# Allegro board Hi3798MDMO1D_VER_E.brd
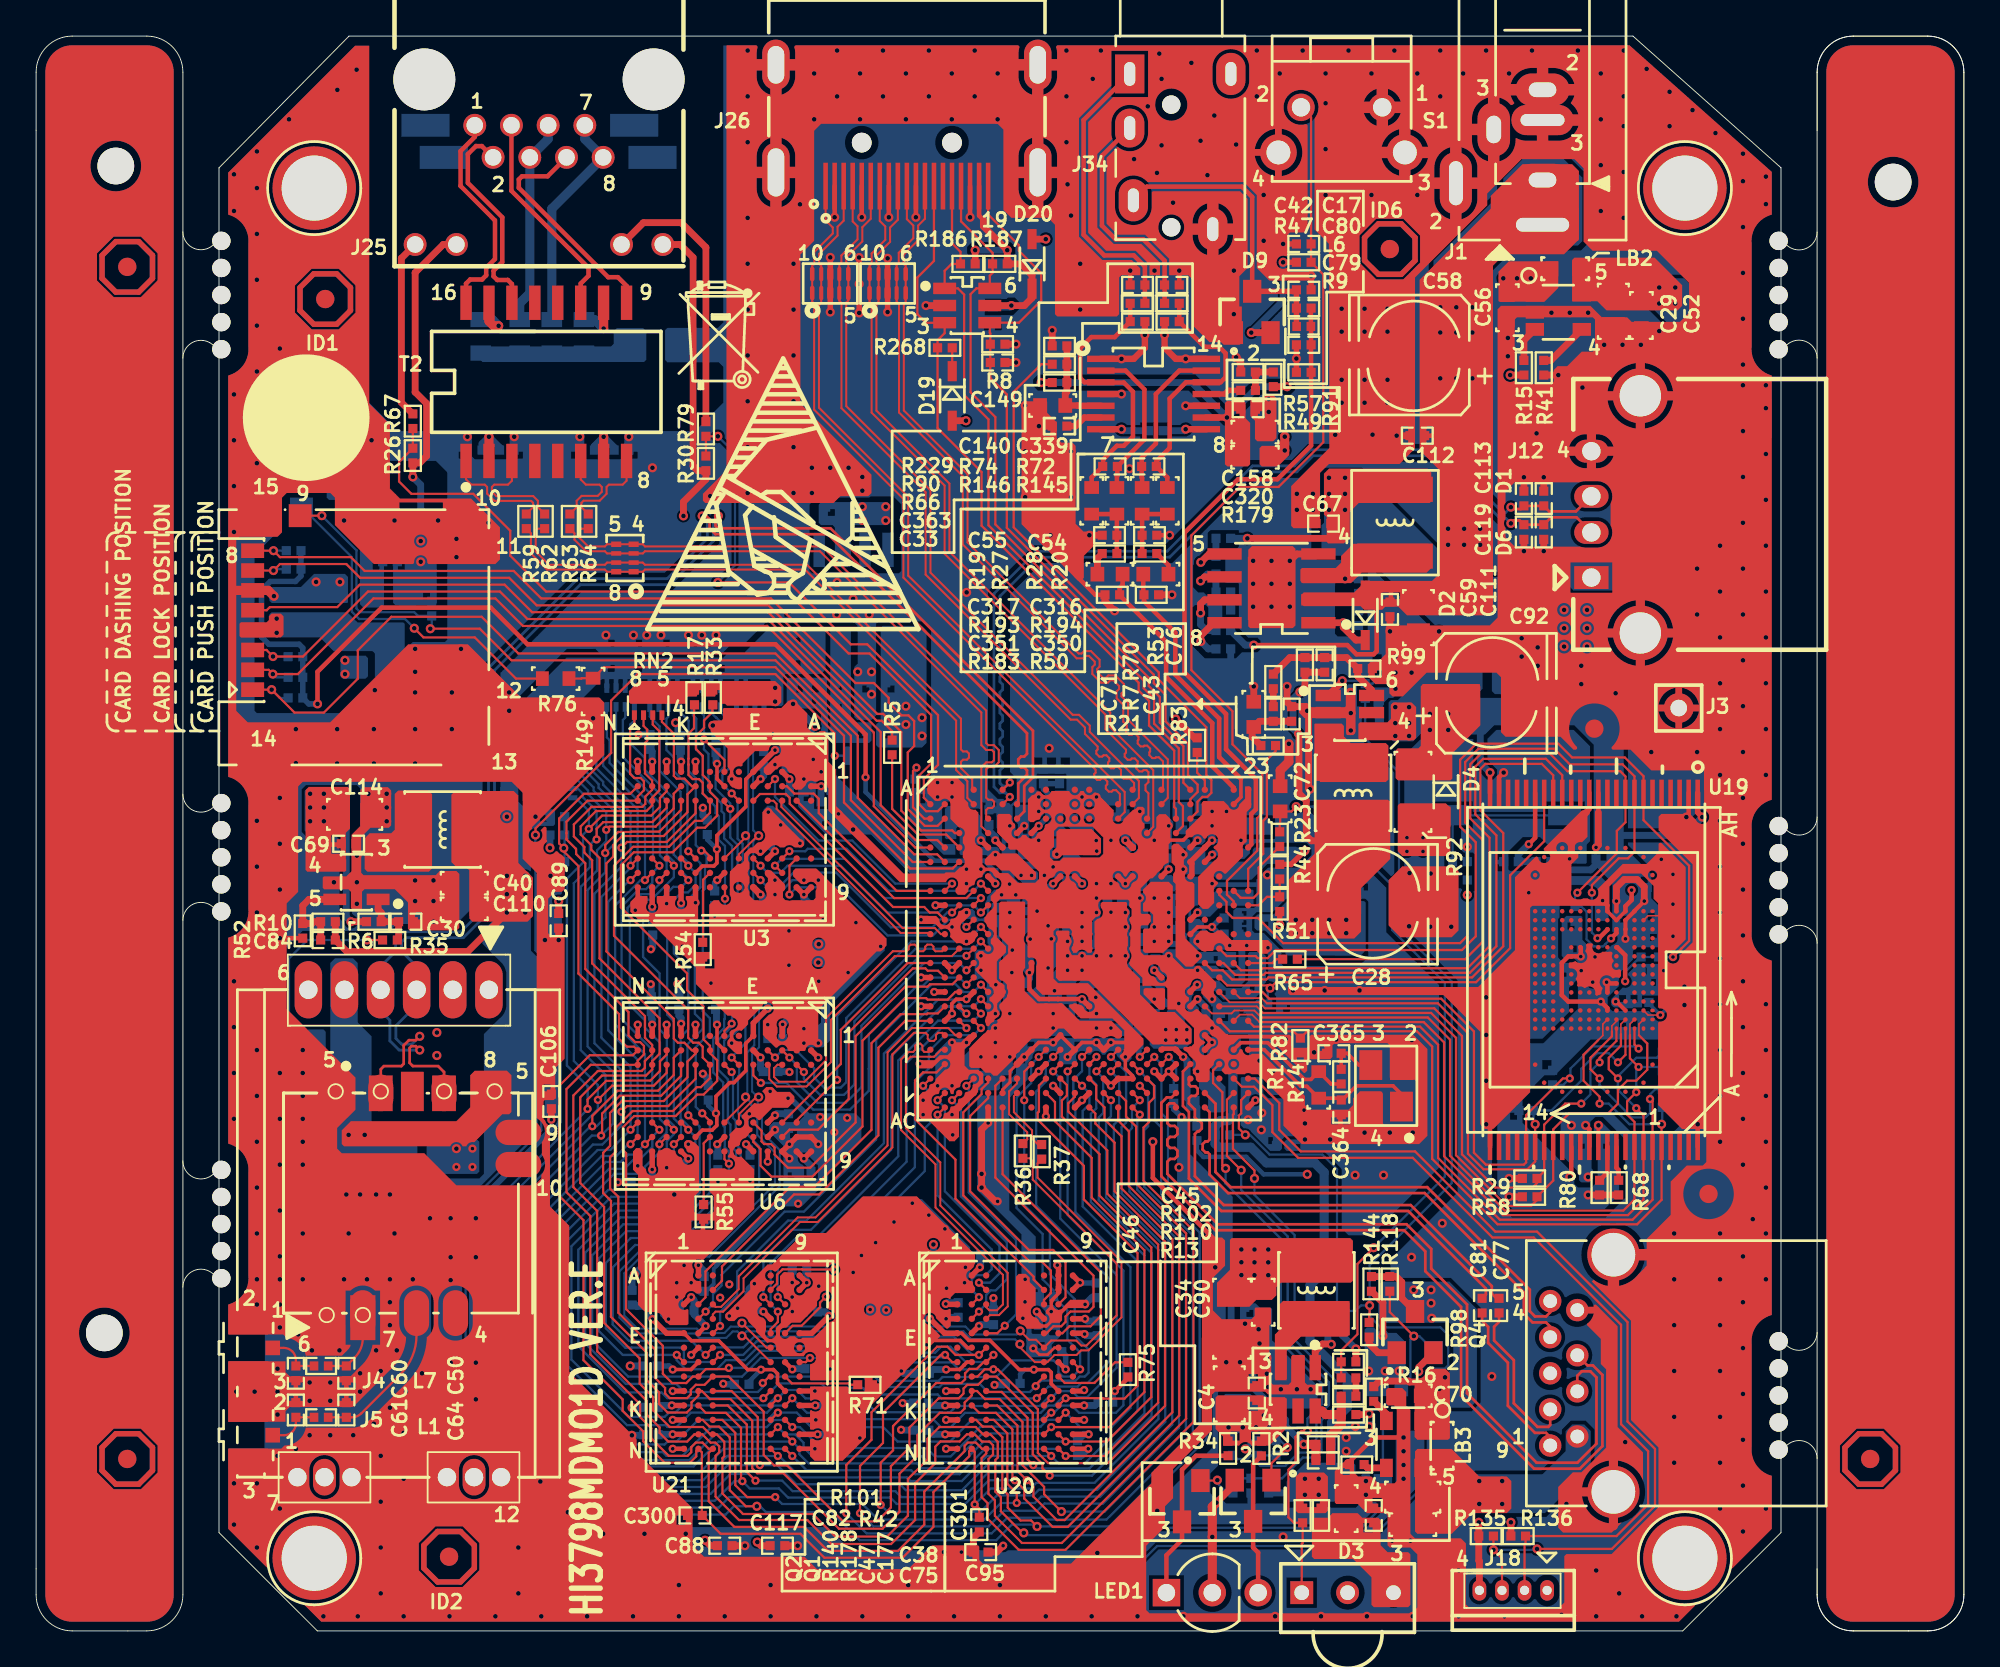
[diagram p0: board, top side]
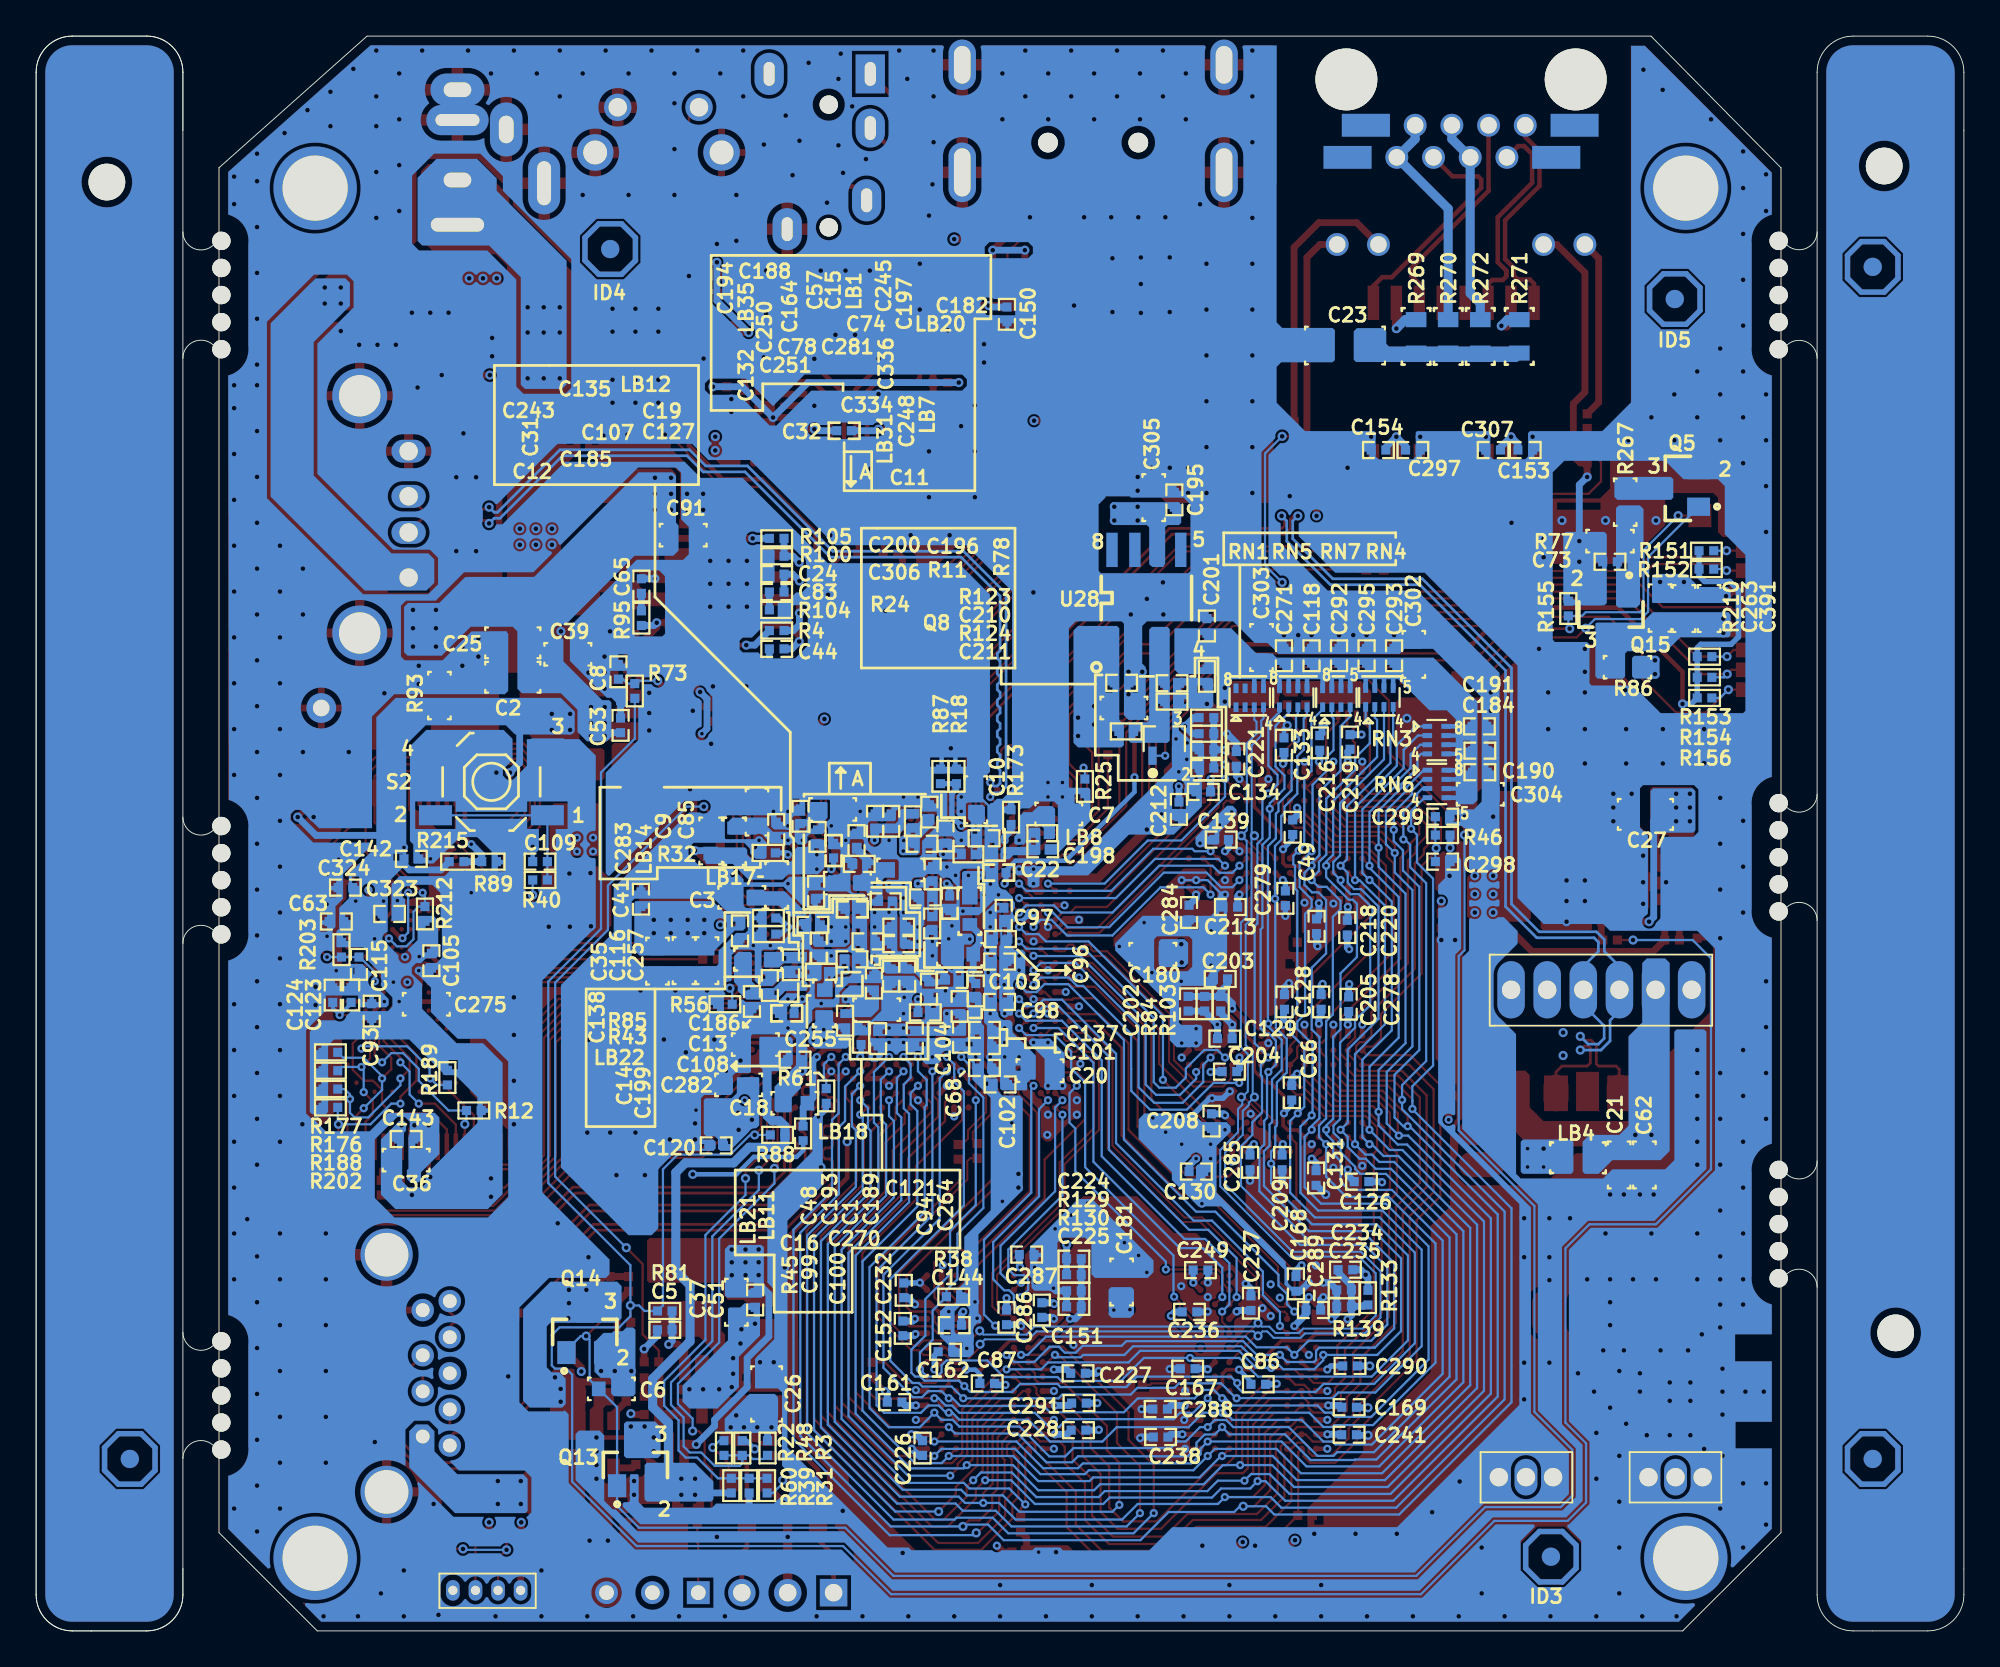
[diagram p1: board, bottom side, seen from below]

Outline 106.76 x 88.35 mm; copper layers: TOP, GND02, POWER03, BOTTOM. Coordinates in mm from the lower left corner of the outline.
Outline path: 98.63,86.35 98.63,83.14 ; 98.63,86.35 arc(99.21,87.76) 100.63,88.35 ; 98.63,86.35 arc(99.21,87.76) 100.63,88.35 ; 98.63,86.35 98.63,83.14 ; 98.63,83.14 98.63,3.43 ; 100.63,88.35 104.76,88.35 ; 100.63,88.35 104.76,88.35 ; 98.63,3.43 98.63,2 ; 98.63,3.43 98.63,2 ; 98.63,2 arc(99.21,0.59) 100.63,0 ; 98.63,2 arc(99.21,0.59) 100.63,0 ; 104.76,88.35 arc(106.17,87.76) 106.76,86.35 ; 104.76,88.35 arc(106.17,87.76) 106.76,86.35 ; 100.63,0 103.71,0 ; 100.63,0 103.71,0 ; 103.71,0 104.76,0 ; 103.71,0 104.76,0 ; 104.76,0 arc(106.17,0.59) 106.76,2 ; 104.76,0 arc(106.17,0.59) 106.76,2 ; 106.76,86.35 106.76,2 ; 106.76,86.35 106.76,2 ; 0,86.35 0,2 arc(0.59,0.59) 2,0 6.13,0 arc(7.54,0.59) 8.13,2 8.13,86.35 arc(7.54,87.76) 6.13,88.35 2,88.35 arc(0.59,87.76) 0,86.35 ; 10.13,81.05 17.33,88.35 88.43,88.35 96.63,81.05 96.63,5.44 91.18,0 15.57,0 10.13,5.45 10.13,81.05

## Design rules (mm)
constraint set DEFAULT: min track width 0.127
net group $5N541: nets 5V0 $5N541
net group $5N549: nets $5N549 STANDBY_PWROFF
net group $7N1630: nets $7N1630 USB_BOOT
net group $8N1514: nets $8N1514 DDR_CLK1P
net group $8N1515: nets $8N1515 DDR_CLK1N
net group $14N708: nets $14N708 USB3_TXP
net group $14N709: nets $14N709 USB3_TXN
net group $17N263: nets $17N263 TX+_PHY0
net group $17N269: nets $17N269 TX-_PHY0
net group DIFF: nets RX+_PHY0 RX-_PHY0
net group DIFFPAIR8: nets DDR_DQS0N DDR_DQS0P
net group DIFFPAIR9: nets DDR_DQS1N DDR_DQS1P
net group DIFFPAIR10: nets DDR_DQS2N DDR_DQS2P
net group DIFFPAIR11: nets DDR_DQS3N DDR_DQS3P
net group DIFFPAIR20: nets USB2_DM USB2_DP
net group DIFFPAIR21: nets $17N178 $17N179
net group DIFFPAIR22: nets $17N175 $17N176
net group DIFFPAIR23: nets USB3_RXN USB3_RXP
net group USB: nets USB3_DM USB3_DP
net group 00: nets GND
net group 01: nets ADAC_VOUTL ADAC_VOUTR MUTE_CTRL
net group 02: nets 1V1_CPU
net group $17N268: nets $17N268
net group $17N270: nets $17N270
net group DDR: nets DDR_ADDR0 DDR_ADDR1 DDR_ADDR2 DDR_ADDR3 DDR_ADDR4 DDR_ADDR5 DDR_ADDR6 DDR_ADDR7 DDR_ADDR8 DDR_ADDR9 DDR_ADDR10 DDR_ADDR11 DDR_ADDR12 DDR_ADDR13 DDR_ADDR14 DDR_ADDR15 DDR_BA0 DDR_BA1 DDR_BA2 DDR_CASN DDR_CKE DDR_CSN DDR_DM0 DDR_DM1 DDR_DM2 DDR_DM3 DDR_DQ0 DDR_DQ1 DDR_DQ2 DDR_DQ3 DDR_DQ4 DDR_DQ5 DDR_DQ6 DDR_DQ7 DDR_DQ8 DDR_DQ9 DDR_DQ10 DDR_DQ11 DDR_DQ12 DDR_DQ13 DDR_DQ14 DDR_DQ15 DDR_DQ16 DDR_DQ17 DDR_DQ18 DDR_DQ19 DDR_DQ20 DDR_DQ21 DDR_DQ22 DDR_DQ23 DDR_DQ24 DDR_DQ25 DDR_DQ26 DDR_DQ27 DDR_DQ28 DDR_DQ29 DDR_DQ30 DDR_DQ31 DDR_ODT DDR_RASN DDR_RESETN DDR_WEN
net group DIFF90: nets USB0_DM USB0_DP USB1_DM USB1_DP
net group POWER: nets 1V1_CORE 1V5_DDR3 3V3_MOS
net group VIN: nets 3V3

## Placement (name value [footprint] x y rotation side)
C1  1NF  [SC0402]  58.52 36.27 270 bottom
C2  22UF  [SC0805]  80.36 52.83 0 bottom
C3  220NF  [SC0603]  67.67 40.64 0 bottom
C4  22UF  [SC0805]  66.07 13.13 90 top
C5  1NF  [SC0402]  71.94 16.68 0 bottom
C6  220NF  [SC0603]  74.9 13.41 0 bottom
C7  220NF  [SC0603]  50.12 45.26 180 bottom
C8  1NF  [SC0402]  74.51 53.13 90 bottom
C9  220NF  [SC0603]  66.84 45.36 90 bottom
C10  220NF  [SC0603]  54.72 46.05 90 bottom
C11  220NF  [SC0603]  55.56 37.49 0 bottom
C12  1NF  [SC0402]  63.28 36.51 0 bottom
C13  220NF  [SC0603]  66.92 32.48 0 bottom
C14  1NF  [SC0402]  66.12 35.76 90 bottom
C15  1NF  [SC0402]  59.41 44.85 90 bottom
C16  220NF  [SC0603]  60.21 34.41 180 bottom
C17  1NF  [SC0402]  70.2 74.3 0 top
C18  220NF  [SC0603]  64.74 29.23 0 bottom
C19  1NF  [SC0402]  58.99 39.01 180 bottom
C20  220NF  [SC0603]  51.16 31.03 180 bottom
C21  220NF  [SC0603]  19.09 25.81 270 bottom
C22  330N  [HSC0402]  53.45 42.01 180 bottom
C23  1NF  [SC1206]  34.27 71.21 0 bottom
C24  1NF  [SC0402]  65.74 58.54 0 bottom
C25  22UF  [SC0805]  80.36 54.74 0 bottom
C26  22UF  [SC0805]  66.3 13.13 90 bottom
C27  22UF  [SC0805]  17.64 45.23 0 bottom
C28  100UF  [SAC6666]  74.29 40.25 0 top
C29  22UF  [SC0805]  87.34 73.1 270 top
C30  1NF  [SC0402]  20.48 39.29 0 top
C31  330N  [HSC0402]  63.41 37.82 270 bottom
C32  330N  [HSC0402]  62.01 66.49 0 bottom
C33  330N  [HSC0402]  56.68 66.74 0 top
C34  1NF  [SC1206]  66.23 17.29 270 top
C35  220NF  [SC0603]  72.35 37.1 270 bottom
C36  220NF  [SC0603]  86.27 26.08 180 bottom
C37  220NF  [SC0603]  67.98 18.21 270 bottom
C38  22UF  [SC0805]  76.23 7.41 180 top
C39  220NF  [SC0603]  77.31 54.1 180 bottom
C40  220NF  [SC0603]  23.71 41.42 180 top
C41  1NF  [SC0402]  73.26 40.53 90 bottom
C42  1NF  [SC0402]  70.2 76.83 0 top
C43  1NF  [SC0402]  69.53 50.8 90 top
C44  1NF  [SC0402]  65.74 54.4 0 bottom
C45  1NF  [SC0402]  72.68 14.91 0 top
C46  1NF  [SC0402]  67.6 13.18 90 top
C47  220NF  [SC0603]  72.55 6.78 90 top
C48  1NF  [SC0402]  60.36 35.89 90 bottom
C49  1NF  [SC0402]  37.17 44.52 90 bottom
C50  1NF  [SC0402]  17.18 14.27 270 top
C51  1NF  [SC0402]  66.94 18.33 270 bottom
C52  220NF  [SC0603]  88.89 72.87 270 top
C53  1NF  [SC0402]  74.39 50.16 90 bottom
C54  1NF  [SC0402]  61.63 64.51 180 top
C55  1NF  [SC0402]  59.47 64.51 180 top
C56  220NF  [SC0603]  81.48 73.3 270 top
C57  1NF  [SC0402]  60.29 44.85 90 bottom
C58  100UF  [SAC6666]  76.05 70.68 180 top
C59  1NF  [SC0402]  74.97 56.59 270 top
C60  1NF  [SC0402]  14.39 14.27 270 top
C61  1NF  [SC0402]  14.39 12.24 90 top
C62  220NF  [SC0603]  17.69 25.81 270 bottom
C63  1NF  [SC0402]  90.13 39.3 0 bottom
C64  1NF  [SC0402]  17.18 12.24 90 top
C65  1NF  [SC0402]  73.24 57.88 90 bottom
C66  1NF  [SC0402]  37.22 29.82 90 bottom
C67  1NF  [SC0402]  71.29 61.34 180 top
C68  1NF  [SC0402]  54.24 31.19 0 bottom
C69  1NF  [SC0402]  17.31 43.61 0 top
C70  220NF  [SC0603]  75.98 13.03 180 top
C71  220NF  [SC0603]  67.43 50.77 90 top
C72  220NF  [SC0603]  68.89 46.1 90 top
C73  1NF  [SC0402]  19.6 59.23 180 bottom
C74  1NF  [SC0402]  57.69 43.61 180 bottom
C75  220NF  [SC0603]  76.23 5.89 180 top
C76  1NF  [SC0402]  71.36 53.51 270 top
C77  1NF  [SC0402]  81.01 18.02 90 top
C78  1NF  [SC0402]  61.17 42.49 0 bottom
C79  1NF  [SC0402]  70.2 71.25 180 top
C80  1NF  [SC0402]  70.2 73.28 180 top
C81  1NF  [SC0402]  80.08 18.02 90 top
C82  1NF  [SC0402]  71.28 9.44 180 top
C83  1NF  [SC0402]  65.74 57.55 0 bottom
C84  1NF  [SC0402]  16.16 38.27 0 top
C85  1NF  [SC0402]  65.77 44.39 90 bottom
C86  1NF  [SC0402]  39.07 13.66 180 bottom
C87  1NF  [SC0402]  54.09 13.71 180 bottom
C88  1NF  [SC0402]  38.13 4.72 0 top
C89  1NF  [SC0402]  28.94 39.34 270 top
C90  220NF  [SC0603]  67.95 18.21 270 top
C91  220NF  [SC0603]  70.93 60.7 180 bottom
C92  100UF  [SAC6666]  80.87 51.94 0 top
C93  1NF  [SC0402]  88.17 34.34 90 bottom
C94  1NF  [SC0402]  55.61 34.59 90 bottom
C95  1NF  [SC0402]  52.31 4.36 180 top
C96  1NF  [SC0402]  53.35 38.32 180 bottom
C97  1NF  [SC0402]  53.17 39.64 270 bottom
C98  1NF  [SC0402]  53.4 34.84 180 bottom
C99  1NF  [SC0402]  60.13 32.81 270 bottom
C100  1NF  [SC0402]  58.1 32.84 270 bottom
C101  1NF  [SC0402]  54.24 32.41 0 bottom
C102  1NF  [SC0402]  53.37 30.27 0 bottom
C103  1NF  [SC0402]  53.4 37.08 180 bottom
C104  1NF  [SC0402]  55.53 32.89 270 bottom
C105  1NF  [SC0402]  84.87 37.13 270 bottom
C106  1NF  [SC0402]  28.53 29.33 90 top
C107  1NF  [SC0402]  60.69 38.2 0 bottom
C108  1NF  [SC0402]  64.73 31.64 180 bottom
C109  1NF  [SC0402]  78.85 42.62 0 bottom
C110  220NF  [SC0603]  23.71 40 180 top
C111  22UF  [SC0805]  76.55 56.13 270 top
C112  1NF  [SC0402]  76.49 66.21 180 top
C113  1NF  [SC0402]  82.39 62.73 90 top
C114  22UF  [SC0805]  17.64 45.23 0 top
C115  1NF  [SC0402]  88.88 36.92 270 bottom
C116  220NF  [SC0603]  70.87 37.13 270 bottom
C117  1NF  [SC0402]  41.06 4.72 0 top
C118  1NF  [SC0402]  36.13 54.02 90 bottom
C119  1NF  [SC0402]  82.39 60.88 270 top
C120  1NF  [SC0402]  69.1 26.89 0 bottom
C121  1NF  [SC0402]  56.04 36.06 180 bottom
C123  1NF  [SC0402]  89.31 35.22 90 bottom
C124  1NF  [SC0402]  90.33 35.22 90 bottom
C126  1NF  [SC0402]  33.36 24.89 180 bottom
C127  1NF  [SC0402]  58.99 38.04 180 bottom
C128  1NF  [SC0402]  37.63 34.84 90 bottom
C129  1NF  [SC0402]  40.93 32.81 180 bottom
C130  1NF  [SC0402]  42.5 25.45 180 bottom
C131  1NF  [SC0402]  35.87 25.09 270 bottom
C132  1NF  [SC0402]  63.56 40.97 90 bottom
C133  1NF  [SC0402]  37.65 49.07 90 bottom
C134  1NF  [SC0402]  42.12 46.48 0 bottom
C135  330N  [HSC0402]  61.55 39.98 180 bottom
C137  1NF  [SC0402]  54.24 33.29 0 bottom
C138  1NF  [SC0402]  67.78 38.78 270 bottom
C139  1NF  [SC0402]  41.13 43.84 0 bottom
C140  1NF  [SC0402]  60.99 74.56 180 top
C142  1NF  [SC0402]  85.98 42.77 180 bottom
C143  1NF  [SC0402]  86.26 27.25 180 bottom
C144  1NF  [SC0402]  55.91 16.94 0 bottom
C149  1NF  [SC0402]  53.25 70.27 0 top
C150  1NF  [SC0402]  52.99 72.93 270 bottom
C151  1NF  [SC0402]  51.06 17.78 270 bottom
C152  1NF  [SC0402]  58.76 16.76 90 bottom
C153  1NF  [SC0402]  24.29 65.42 180 bottom
C154  1NF  [SC0402]  32.42 65.42 0 bottom
C158  1NF  [SC0402]  67.12 67.68 0 top
C161  1NF  [SC0402]  59.22 12.67 0 bottom
C162  1NF  [SC0402]  56.4 15.46 180 bottom
C164  1NF  [SC0402]  61.32 43.79 90 bottom
C167  1NF  [SC0402]  42.99 14.52 0 bottom
C168  1NF  [SC0402]  36.99 19.22 270 bottom
C169  1NF  [SC0402]  34.04 12.39 180 bottom
C177  1NF  [SC0402]  74.08 6.4 90 top
C180  220NF  [SC0603]  44.92 37.49 0 bottom
C181  220NF  [SC0603]  46.64 19.32 90 bottom
C182  1NF  [SC0402]  54.26 43.91 180 bottom
C184  1NF  [SC0402]  26.81 48.76 180 bottom
C185  1NF  [SC0402]  61.58 37.21 180 bottom
C186  1NF  [SC0402]  67.12 34.87 270 bottom
C188  220NF  [SC0603]  62.65 45.51 180 bottom
C189  1NF  [SC0402]  57.31 35.56 270 bottom
C190  1NF  [SC0402]  26.81 47.57 180 bottom
C191  1NF  [SC0402]  26.83 50.11 180 bottom
C193  1NF  [SC0402]  59.41 36.27 270 bottom
C194  1NF  [SC0402]  64.42 45.13 90 bottom
C195  1NF  [SC0402]  43.72 62.66 90 bottom
C196  1NF  [SC0402]  43.85 52.5 180 bottom
C197  1NF  [SC0402]  56.4 44.04 90 bottom
C198  1NF  [SC0402]  51.01 43.3 180 bottom
C199  1NF  [SC0402]  64.96 36.9 270 bottom
C200  1NF  [SC0402]  46.64 52.52 180 bottom
C201  1NF  [SC0402]  41.92 55.67 90 bottom
C202  1NF  [SC0402]  42.96 34.74 90 bottom
C203  1NF  [SC0402]  41.18 36.11 0 bottom
C204  1NF  [SC0402]  40.67 30.98 0 bottom
C205  1NF  [SC0402]  35.59 34.84 90 bottom
C208  1NF  [SC0402]  41.66 28.24 270 bottom
C209  1NF  [SC0402]  37.75 25.95 270 bottom
C210  1NF  [SC0402]  41.94 49.7 180 bottom
C211  1NF  [SC0402]  41.94 47.8 0 bottom
C212  1NF  [SC0402]  43.47 45.51 270 bottom
C213  1NF  [SC0402]  40.62 40.1 0 bottom
C216  1NF  [SC0402]  35.67 49.2 90 bottom
C218  1NF  [SC0402]  35.85 39.04 270 bottom
C219  1NF  [SC0402]  33.99 49.25 90 bottom
C220  1NF  [SC0402]  34.15 38.96 270 bottom
C221  1NF  [SC0402]  40.29 48.31 90 bottom
C224  1NF  [SC0402]  49.28 20.62 180 bottom
C225  1NF  [SC0402]  49.28 17.95 0 bottom
C226  1NF  [SC0402]  57.67 10.13 270 bottom
C227  1NF  [SC0402]  49.06 14.27 180 bottom
C228  1NF  [SC0402]  49.03 11.12 180 bottom
C232  1NF  [SC0402]  58.71 18.87 270 bottom
C234  1NF  [SC0402]  34.25 20.01 0 bottom
C235  1NF  [SC0402]  34.32 18.89 0 bottom
C236  1NF  [SC0402]  42.88 17.67 180 bottom
C237  1NF  [SC0402]  39.48 18.16 90 bottom
C238  1NF  [SC0402]  44.48 10.74 0 bottom
C241  1NF  [SC0402]  34.04 10.87 180 bottom
C243  1NF  [SC0402]  63.74 39.11 0 bottom
C245  1NF  [SC0402]  57.29 45.36 90 bottom
C248  330N  [HSC0402]  56.17 40.31 270 bottom
C249  1NF  [SC0402]  42.27 19.99 180 bottom
C250  330N  [HSC0402]  62.59 43.23 270 bottom
C251  220NF  [SC0603]  61.83 41.42 0 bottom
C255  330N  [HSC0402]  65.19 34.21 180 bottom
C257  220NF  [SC0603]  69.6 37.13 270 bottom
C263  220NF  [SC0603]  15.5 56.64 90 bottom
C264  1NF  [SC0402]  54.72 35.45 270 bottom
C270  1NF  [SC0402]  57.51 34.26 180 bottom
C271  1NF  [SC0402]  37.65 54.02 90 bottom
C275  220NF  [SC0603]  85.15 34.71 180 bottom
C278  1NF  [SC0402]  34.07 34.72 90 bottom
C279  1NF  [SC0402]  37.58 40.58 270 bottom
C281  220NF  [SC0603]  58.89 42.16 180 bottom
C282  220NF  [SC0603]  67.85 30.25 0 bottom
C283  220NF  [SC0603]  69.4 43.76 90 bottom
C284  1NF  [SC0402]  42.91 39.8 270 bottom
C285  1NF  [SC0402]  39.53 25.95 270 bottom
C286  1NF  [SC0402]  53.02 17.37 90 bottom
C287  1NF  [SC0402]  51.9 20.85 180 bottom
C288  1NF  [SC0402]  44.51 12.29 0 bottom
C289  1NF  [SC0402]  36.03 17.78 180 bottom
C290  1NF  [SC0402]  33.99 14.68 180 bottom
C291  1NF  [SC0402]  49.01 12.62 180 bottom
C292  1NF  [SC0402]  34.6 54.02 90 bottom
C293  1NF  [SC0402]  31.56 54.02 90 bottom
C295  1NF  [SC0402]  33.08 54.02 90 bottom
C297  1NF  [SC0402]  30.51 65.42 180 bottom
C298  1NF  [SC0402]  28.86 42.62 180 bottom
C299  1NF  [SC0402]  28.86 45.11 180 bottom
C300  1NF  [SC0402]  36.48 6.4 180 top
C301  1NF  [SC0402]  52.23 5.89 270 top
C302  220NF  [SC0603]  30.46 54.1 90 bottom
C303  220NF  [SC0603]  38.9 54.48 90 bottom
C304  220NF  [SC0603]  26.78 46.35 180 bottom
C305  220NF  [SC0603]  44.87 62.78 90 bottom
C306  220NF  [SC0603]  46.52 51.13 180 bottom
C307  1NF  [SC0402]  26.07 65.42 0 bottom
C316  1NF  [SC0402]  61.65 60.7 0 top
C317  1NF  [SC0402]  59.44 60.7 180 top
C320  220NF  [SC0603]  67.5 66.41 0 top
C323  1NF  [SC0402]  87.18 39.72 180 bottom
C324  1NF  [SC0402]  89.63 41.18 0 bottom
C334  1NF  [SC0402]  57.51 40.64 0 bottom
C336  1NF  [SC0402]  57.11 41.93 90 bottom
C339  1NF  [SC0402]  62.9 74.56 0 top
C350  220NF  [SC0603]  62.01 58.54 180 top
C351  220NF  [SC0603]  59.47 58.54 180 top
C363  220NF  [SC0603]  56.3 67.88 180 top
C364  1NF  [SC0402]  72.28 29 270 top
C365  1NF  [SC0402]  71.87 32 180 top
C391  220NF  [SC0603]  14.11 56.64 90 bottom
D1  1NF  [SC0402]  83.49 62.73 90 top
D2  D_A  [HSOD323A]  73.6 56.26 270 top
D3  IR  [SEN3-100C]  72.63 2.12 0 top
D4  D_A  [HSOD323A]  78.07 46.48 90 top
D6  1NF  [SC0402]  83.49 60.88 270 top
D9  D2-3_A  [SOT23]  67.34 73.07 0 top
D19  D_A  [HSOD323A]  50.73 68.41 90 top
D20  D_A  [HSOD323A]  55.15 75.73 270 top
ID1  PCB_MARKPOINT_A  [ID-BOARD]  16.01 73.78 0 top
ID2  PCB_MARKPOINT_A  [ID-BOARD]  22.87 4.11 0 top
ID3  PCB_MARKPOINT_A  [ID-BOARD]  22.87 4.11 180 bottom
ID4  PCB_MARKPOINT_A  [ID-BOARD]  74.96 76.55 180 bottom
ID5  PCB_MARKPOINT_A  [ID-BOARD]  16.01 73.78 180 bottom
ID6  PCB_MARKPOINT_A  [ID-BOARD]  74.96 76.55 0 top
J1  DC_012_HW  [PWC3-RF-A]  83.42 77.9 90 top
J2  VALUE  [SIP12-2_0MM-1827]  20.07 22.02 270 top
J3  NC  [SIP-1P]  90.97 51.13 0 top
J4  51_3612_50_H  [HSCOX-AMC-TM-A]  11.75 15.68 270 top
J5  51_3612_50_H  [HSCOX-AMC-TM-A]  11.75 10.84 270 top
J10  NC  [DC-002]  83.42 80.38 0 top
J12  SMDUSBA  [USB4-1415]  86.13 58.35 90 top
J13  USB3_ATYPE  [USB3_0_9P_DIP_MAINSUPER]  85.35 10.77 90 top
J18  SDW12501_4A_HW  [WBC0104-49T]  83.68 2.24 180 top
J21  5031820832  [MICRO_SD8-PUSH]  17.6 55.04 270 top
J25  406533_1  [MJ8-RLY]  24.29 83.41 0 top
J26  0  [WBC0119-20R-A]  48.22 85.19 180 top
J34  8967_3506ADT_M_A  [VAF6-1107]  60.56 86.25 270 top
L1  1NH  [SL0402]  15.78 11.83 0 top
L2  3.3UH  [SWPA4020S]  72.93 46.43 270 top
L3  3.3UH  [SWPA4020S]  70.9 18.87 90 top
L4  3.3UH  [SWPA4020S]  22.51 44.39 0 top
L5  6.8UH  [SWPA5040S]  75.25 61.39 90 top
L6  1NH  [SL0402]  70.2 72.26 180 top
L7  1NH  [SL0402]  15.78 14.68 0 top
LB1  1NH  [SL0402]  58.2 44.85 270 bottom
LB2  MGLB1608_030T_LF  [SL0603]  84.68 75.46 180 top
LB3  MGLB1608_030T_LF  [SL0603]  77.86 10.26 90 top
LB4  MGLB2012_220T_LF  [SL0805]  21.37 26.21 0 bottom
LB7  MGLB1608_030T_LF  [SL0603]  55.05 39.87 90 bottom
LB8  1NH  [SL0402]  51.04 44.19 0 bottom
LB11  1NH  [SL0402]  61.96 33.8 90 bottom
LB12  1NH  [SL0402]  59.71 40.41 180 bottom
LB14  MGLB1608_030T_LF  [SL0603]  68.08 43.74 90 bottom
LB17  MGLB1608_030T_LF  [SL0603]  65.74 41.32 90 bottom
LB18  1NH  [SL0402]  64.28 27.56 90 bottom
LB20  1NH  [SL0402]  55.13 43.02 180 bottom
LB21  MGLB1608_030T_LF  [SL0603]  63.1 34.76 90 bottom
LB22  MGLB1608_030T_LF  [SL0603]  66.79 37.21 0 bottom
LB31  1NH  [SL0402]  57.13 39.19 90 bottom
LB35  1NH  [SL0402]  63.48 43.99 90 bottom
LED1  209_3SYGSURC_S530_A3HW  [LED3C-100C]  62.59 2.12 0 top
M20  M3_HOLE_A  [HOLE182-142]  91.3 4.02 0 top
M21  M3_HOLE_A  [HOLE182-142]  15.4 4.02 0 top
M22  M3_HOLE_A  [HOLE182-142]  91.3 79.93 0 top
M23  M3_HOLE_A  [HOLE182-142]  15.4 79.93 0 top
NOREF  -  []  -204.22 -199.15 0 top
NOREF#2  -  [unnamed#2]  5.05 75.56 0 top
NOREF#3  -  []  140.57 179.7 0 top
NOREF#4  -  []  41.88 59.94 0 top
NOREF#5  -  [unnamed#2]  5.05 9.53 0 top
NOREF#6  -  []  138.77 142.52 180 top
NOREF#7  -  []  -0.03 22.99 0 top
NOREF#8  -  [unnamed#3]  9.13 22.54 270 top
NOREF#9  -  []  -45.41 169.08 0 top
NOREF#10  -  [unnamed#3]  97.63 41.59 90 top
NOREF#11  -  [unnamed#3]  97.63 13.04 90 top
NOREF#12  -  []  10.13 8.64 0 top
NOREF#13  -  [unnamed#4]  102.84 80.26 0 top
NOREF#14  -  []  19.53 0 90 top
NOREF#15  -  [unnamed#2]  101.57 9.53 0 top
NOREF#16  -  [unnamed#3]  9.13 74 270 top
NOREF#17  -  [unnamed#4]  3.78 16.51 0 top
NOREF#18  -  []  15.46 67.44 0 top
NOREF#19  -  [unnamed#3]  97.63 74 90 top
NOREF#20  -  []  104.62 88.65 0 top
NOREF#21  -  [unnamed#3]  9.13 42.86 270 top
NOREF#22  -  [unnamed#4]  4.41 81.15 0 top
NOREF#23  -  []  40.35 71.88 0 top
NOREF#24  -  [unnamed#2]  5.05 75.56 180 bottom
NOREF#25  -  [unnamed#2]  5.05 9.53 180 bottom
NOREF#26  -  [unnamed#2]  101.57 9.53 180 bottom
Q1  D2-3_A  [SOT23]  67.39 7.21 180 top
Q2  D2-3_A  [SOT23]  63.46 7.18 180 top
Q4  D2-3_A  [SOT23]  76.36 16.56 0 top
Q5  D2-3_A  [SOT23]  15.84 63.29 90 bottom
Q8  FETN-GSD  [HSOT-SC70]  44.28 49.42 180 bottom
Q13  D2-3_A  [SOT23]  73.57 9.19 180 bottom
Q14  D2-3_A  [SOT23]  76.37 16.56 180 bottom
Q15  D2-3_A  [SOT23]  19.54 56.31 0 bottom
R1  5.1K  [SR0603]  71.03 30.25 270 top
R2  0/NC  [SR0402]  67.85 10.1 270 top
R3  0/NC  [SR0402]  66.25 10.13 270 bottom
R4  0/NC  [SR0402]  65.74 55.42 180 bottom
R5  0/NC  [SR0402]  47.41 48.94 270 top
R6  0/NC  [SR0402]  18.7 39.29 0 top
R7  0/NC  [SR0402]  68.51 50.8 270 top
R8  0/NC  [SR0402]  53.25 71.28 180 top
R9  0/NC  [SR0402]  70.2 69.72 180 top
R10  0/NC  [SR0402]  16.16 39.29 0 top
R11  0/NC  [SR0402]  43.85 51.48 0 bottom
R12  0/NC  [SR0402]  82.52 28.83 0 bottom
R13  0/NC  [SR0402]  72.68 11.98 180 top
R14  0/NC  [SR0402]  72.27 30.7 90 top
R15  0/NC  [SR0402]  82.39 69.98 270 top
R16  0/NC  [SR0402]  74.08 13.13 90 top
R17  0/NC  [SR0402]  36.46 51.71 90 top
R18  0/NC  [SR0402]  55.79 47.34 270 bottom
R19  5.1K  [SR0603]  58.45 62.6 90 top
R20  5.1K  [SR0603]  62.65 62.6 270 top
R21  0/NC  [SR0402]  68.23 49.04 0 top
R22  0/NC  [SR0402]  68.66 10.13 90 bottom
R23  0/NC  [SR0402]  68.87 43.86 270 top
R24  0/NC  [SR0402]  46.39 49.83 0 bottom
R25  0/NC  [SR0402]  48.68 46.78 90 bottom
R26  0/NC  [SR0402]  20.86 65.11 90 top
R27  5.1K  [SR0603]  59.85 62.6 90 top
R28  5.1K  [SR0603]  61.25 62.6 270 top
R29  0/NC  [SR0402]  82.71 25.07 0 top
R30  0/NC  [SR0402]  37.09 64.68 90 top
R31  0/NC  [SR0402]  66.28 8.05 270 bottom
R32  0/NC  [SR0402]  66.23 43.1 180 bottom
R33  0/NC  [SR0402]  37.47 51.71 90 top
R34  0/NC  [SR0402]  66.01 10.11 270 top
R35  0/NC  [SR0402]  19.59 38.27 0 top
R36  0/NC  [SR0402]  54.64 26.59 90 top
R37  0/NC  [SR0402]  55.69 26.54 90 top
R38  0/NC  [SR0402]  55.94 18.51 0 bottom
R39  0/NC  [SR0402]  67.27 8.05 270 bottom
R40  0/NC  [SR0402]  78.85 41.6 0 bottom
R41  0/NC  [SR0402]  83.49 69.98 90 top
R42  0/NC  [SR0402]  73.14 9.22 0 top
R43  0/NC  [SR0402]  66.2 38.6 0 bottom
R44  0/NC  [SR0402]  68.87 42.06 90 top
R45  0/NC  [SR0402]  61.07 32.89 90 bottom
R46  0/NC  [SR0402]  28.86 44.09 180 bottom
R47  0/NC  [SR0402]  70.2 75.82 0 top
R48  0/NC  [SR0402]  67.65 10.13 90 bottom
R49  0/NC  [SR0402]  67.12 68.72 0 top
R50  0/NC  [SR0402]  61.76 57.4 0 top
R51  0/NC  [SR0402]  68.87 40.26 270 top
R52  0/NC  [SR0402]  14.77 38.78 270 top
R53  0/NC  [SR0402]  70.27 53.51 270 top
R54  0/NC  [SR0402]  36.91 37.74 90 top
R55  0/NC  [SR0402]  36.97 23.21 90 top
R56  0/NC  [SR0402]  68.61 34.72 180 bottom
R57  0/NC  [SR0402]  67.12 69.74 180 top
R58  0/NC  [SR0402]  82.71 24.05 0 top
R59  0/NC  [SR0402]  27.15 61.47 90 top
R60  0/NC  [SR0402]  68.26 8.05 90 bottom
R61  0/NC  [SR0402]  63 29.64 90 bottom
R62  0/NC  [SR0402]  28.16 61.47 90 top
R63  0/NC  [SR0402]  29.56 61.47 90 top
R64  0/NC  [SR0402]  30.57 61.47 90 top
R65  0/NC  [SR0402]  69.44 37.21 180 top
R66  0/NC  [SR0402]  56.68 69.15 180 top
R67  0/NC  [SR0402]  20.86 67.02 270 top
R68  0/NC  [SR0402]  87.64 24.56 270 top
R70  0/NC  [SR0402]  68.51 52.6 270 top
R71  0/NC  [SR0402]  45.91 13.64 180 top
R72  560  [HSR0402]  62.9 73.55 180 top
R73  0/NC  [SR0402]  73.6 52.07 90 bottom
R74  560  [HSR0402]  60.99 73.55 180 top
R75  0/NC  [SR0402]  60.46 14.47 90 top
R76  5.1K  [SR0603]  28.77 52.76 180 top
R77  5.1K  [SR0603]  19.6 60.37 180 bottom
R78  0/NC  [SR0402]  41.92 52.88 90 bottom
R79  0/NC  [SR0402]  37.09 66.58 270 top
R80  0/NC  [SR0402]  86.58 24.56 90 top
R81  0/NC  [SR0402]  71.94 17.72 180 bottom
R82  0/NC  [SR0402]  70.01 32.43 270 top
R83  0/NC  [SR0402]  64.3 49.07 90 top
R84  0/NC  [SR0402]  42.05 34.74 90 bottom
R85  0/NC  [SR0402]  66.2 39.49 0 bottom
R86  5.1K  [SR0603]  18.63 53.39 0 bottom
R87  0/NC  [SR0402]  56.68 47.34 270 bottom
R88  0/NC  [SR0402]  65.69 27.48 180 bottom
R89  0/NC  [SR0402]  81.67 42.62 180 bottom
R90  0/NC  [SR0402]  56.68 70.17 0 top
R91  0/NC  [SR0402]  68.51 69.33 90 top
R92  -  [SR1206]  76.24 46.48 90 top
R93  5.1K  [SR0603]  84.42 51.82 90 bottom
R95  0/NC  [SR0402]  73.24 56.1 90 bottom
R98  0/NC  [SR0402]  73.82 16.68 270 top
R99  0/NC  [SR0402]  73.59 53.31 180 top
R100  0/NC  [SR0402]  65.74 59.53 0 bottom
R101  0/NC  [SR0402]  71.28 10.33 180 top
R102  0/NC  [SR0402]  72.68 14.02 180 top
R103  0/NC  [SR0402]  41.16 34.74 270 bottom
R104  0/NC  [SR0402]  65.74 56.56 180 bottom
R105  0/NC  [SR0402]  65.74 60.52 0 bottom
R110  0/NC  [SR0402]  72.68 13 0 top
R118  0/NC  [SR0402]  74.96 19.22 90 top
R123  0/NC  [SR0402]  41.94 50.59 180 bottom
R124  0/NC  [SR0402]  41.94 48.81 0 bottom
R129  0/NC  [SR0402]  49.28 19.73 180 bottom
R130  0/NC  [SR0402]  49.28 18.84 0 bottom
R133  0/NC  [SR0402]  33 18.46 270 bottom
R135  0/NC  [SR0402]  80.3 5.25 0 top
R136  0/NC  [SR0402]  82.08 5.25 0 top
R139  0/NC  [SR0402]  34.32 17.98 0 bottom
R140  0/NC  [SR0402]  70.14 6.4 90 top
R144  0/NC  [SR0402]  73.95 19.22 90 top
R145  0/NC  [SR0402]  62.9 72.53 180 top
R146  0/NC  [SR0402]  60.99 72.53 0 top
R149  5.1K  [SR0603]  30.84 52.04 270 top
R151  0/NC  [SR0402]  14.26 59.84 180 bottom
R152  0/NC  [SR0402]  14.26 58.82 180 bottom
R153  0/NC  [SR0402]  14.36 53.97 180 bottom
R154  0/NC  [SR0402]  14.36 52.83 180 bottom
R155  0/NC  [SR0402]  21.91 56.64 270 bottom
R156  0/NC  [SR0402]  14.36 51.68 180 bottom
R173  0/NC  [SR0402]  52.76 45.08 90 bottom
R176  0/NC  [SR0402]  90.46 31.03 180 bottom
R177  0/NC  [SR0402]  90.46 32.05 180 bottom
R178  0/NC  [SR0402]  71.15 6.4 90 top
R179  5.1K  [SR0603]  67.5 65.01 180 top
R183  0/NC  [SR0402]  59.6 57.4 180 top
R186  0/NC  [SR0402]  51.6 75.73 0 top
R187  0/NC  [SR0402]  53.37 75.73 0 top
R188  0/NC  [SR0402]  90.46 30.02 180 bottom
R189  0/NC  [SR0402]  83.98 30.65 270 bottom
R193  0/NC  [SR0402]  59.44 59.68 0 top
R194  0/NC  [SR0402]  61.65 59.68 0 top
R202  0/NC  [SR0402]  90.46 29 180 bottom
R203  0/NC  [SR0402]  89.85 37.74 270 bottom
R210  5.1K  [SR0603]  16.83 56.66 90 bottom
R212  0/NC  [SR0402]  85.22 39.72 90 bottom
R215  0/NC  [SR0402]  83.47 42.62 180 bottom
R229  0/NC  [SR0402]  56.68 71.19 180 top
R267  5.1K  [SR0603]  18.76 62.53 90 bottom
R268  0/NC  [SR0402]  50.33 71.08 180 top
R269  75  [SR0805]  30.34 71.72 90 bottom
R270  75  [SR0805]  28.56 71.72 90 bottom
R271  75  [SR0805]  24.62 71.72 90 bottom
R272  75  [SR0805]  26.78 71.72 90 bottom
RN1  51  [SRN8-0804]  39.55 51.69 180 bottom
RN2  51  [SRN8-0804]  33.89 51.25 0 top
RN3  51  [SRN8-0804]  29.19 49.35 270 bottom
RN4  51  [SRN8-0804]  32.37 51.71 180 bottom
RN5  51  [SRN8-0804]  37.14 51.69 180 bottom
RN6  51  [SRN8-0804]  29.19 46.92 270 bottom
RN7  51  [SRN8-0804]  34.75 51.69 180 bottom
S1  MS-156  [TSW4-RG-C]  74.55 84.4 180 top
S2  TMG_533_T_R  [SPSW6-T]  81.54 47.04 0 bottom
T2  H1102T  [STFM16-50-285]  28.25 69.19 0 top
U1  VALUE  [TFBGA395-32-2323]  58.32 37.8 270 top
U2  CDT-CELKF04  [CDTWIFI]  20.59 23.69 90 top
U3  K4B4G0846A-HCK0  [BGA78-32-1309I]  38.12 44.39 180 top
U4  CS0806U  [SOT23A-6L]  51.56 73.42 270 top
U5  DIO2103_SGM8903  [SGM8903]  61.88 68.52 270 top
U6  K4B4G0846A-HCK0  [BGA78-32-1309I]  38.12 29.76 180 top
U7  NC  [CDTWIFI10]  20.21 23.71 90 top
U8  -  [RN8-0402]  32.61 59.44 90 top
U10  NC  [SOT23-5]  84.3 73.05 270 top
U11  EA8109_SY8032  [SOT23_6]  72.75 50.87 270 top
U12  NC  [SOT23-5]  75.73 10.33 180 top
U13  EA8109_SY8032  [SOT23_6]  69.88 13.38 180 top
U14  EA8253_ETA1486_MP1484  [SOIC8N]  68.41 57.76 90 top
U15  EA8108_SY8089A_ETA3409  [SOT23_5]  17.74 41.47 90 top
U19  NC  [SOP48-20-720B]  86.26 36.62 180 top
U20  K4B4G0846A-HCK0  [BGA78-32-1309I]  54.21 14.89 270 top
U21  K4B4G0846A-HCK0  [BGA78-32-1309I]  39.08 14.89 270 top
U22  EMMC  [BGA169-BGA153-0_5MM]  86.26 36.62 90 top
U23  CS0806S  [DFN2510P10E]  43.98 74.64 0 top
U24  CS0806S  [DFN2510P10E]  47.15 74.64 0 top
U28  RTL9199  [SOP8H-50-200]  45.27 57.22 180 bottom
X2  24MHZ  [X288]  74.76 30.2 90 top

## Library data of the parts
C1 C5 C8 C12 C14 C15 C17 C19 C24 C30 C41-C46 C48-C51 C53-C55 C57 C59-C61 C63-C69 C73 C74 C76-C89 C93-C109 C112 C113 C115 C117-C121 C123 C124 C126-C134 C137-C140 C142-C144 C149-C154 C158 C161 C162 C167-C169 C177 C182 C184-C186 C189-C191 C193-C205 C208-C213 C216 C218-C221 C224-C228 C232 C234-C238 C241 C243 C245 C249 C264 C270 C271 C278 C279 C284-C293 C295 C297-C301 C307 C316 C317 C323 C324 C334 C336 C339 C364 C365 D1 D6 = SC0402
C2 C4 C25-C27 C29 C38 C111 C114 = SC0805
C3 C6 C7 C9-C11 C13 C16 C18 C20 C21 C35-C37 C39 C40 C47 C52 C56 C62 C70-C72 C75 C90 C91 C110 C116 C180 C181 C188 C251 C257 C263 C275 C281-C283 C302-C306 C320 C350 C351 C363 C391 = SC0603
C22 C31-C33 C135 C248 C250 C255 = HSC0402
C23 C34 = SC1206
C28 C58 C92 = SAC6666
C164 = SC0402: signal model: SC0402_10PF/NC
D2 D4 D19 D20 = HSOD323A
D3 = SEN3-100C
D9 Q1 Q2 Q4 Q5 Q13-Q15 = SOT23
ID1-ID6 = ID-BOARD
J1 = PWC3-RF-A
J2 = SIP12-2_0MM-1827
J3 = SIP-1P
J4 J5 = HSCOX-AMC-TM-A
J10 = DC-002
J12 = USB4-1415
J13 = USB3_0_9P_DIP_MAINSUPER
J18 = WBC0104-49T
J21 = MICRO_SD8-PUSH
J25 = MJ8-RLY
J26 = WBC0119-20R-A
J34 = VAF6-1107
L1 L6 L7 LB1 LB8 LB11 LB12 LB18 LB20 LB31 LB35 = SL0402
L2-L4 = SWPA4020S
L5 = SWPA5040S
LB2 LB3 LB7 LB14 LB17 LB21 LB22 = SL0603
LB4 = SL0805
LED1 = LED3C-100C
M20-M23 = HOLE182-142
Q8 = HSOT-SC70
R1 R19 R20 R27 R28 R76 R77 R86 R93 R149 R179 R210 R267 = SR0603
R2-R18 R21-R26 R30-R35 R39-R44 R47-R53 R56 R57 R60 R61 R65-R68 R70 R71 R73 R75 R78-R85 R87-R91 R95 R99-R105 R110 R118 R123 R124 R129 R130 R133 R139 R145 R146 R151-R156 R173 R176 R177 R183 R186-R189 R193 R194 R202 R203 R212 R229 R268 = SR0402
R29 R178 = SR0402: signal model: SR0402_75
R36-R38 R45 R46 = SR0402: signal model: SR0402_33
R54 R55 = SR0402: signal model: SR0402_240
R58 R98 R135 R136 R140 = SR0402: signal model: SR0402_10K
R59 R62-R64 = SR0402: signal model: SR0402_0/NC
R72 R74 = HSR0402
R92 = SR1206
R144 R215 = SR0402: signal model: SR0402_4.7K
R269-R272 = SR0805
RN1-RN7 = SRN8-0804
S1 = TSW4-RG-C
S2 = SPSW6-T
T2 = STFM16-50-285
U1 = TFBGA395-32-2323
U2 = CDTWIFI
U3 U6 U20 U21 = BGA78-32-1309I
U4 = SOT23A-6L
U5 = SGM8903
U7 = CDTWIFI10
U8 = RN8-0402
U10 U12 = SOT23-5
U11 U13 = SOT23_6
U14 = SOIC8N
U15 = SOT23_5
U19 = SOP48-20-720B
U22 = BGA169-BGA153-0_5MM
U23 U24 = DFN2510P10E
U28 = SOP8H-50-200
X2 = X288

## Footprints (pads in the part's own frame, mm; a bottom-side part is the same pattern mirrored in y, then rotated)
BGA78-32-1309I
  round 0.356 smd: A1(-4.8,-3.2) A2(-4.8,-2.4) A3(-4.8,-1.6) A7(-4.8,1.6) A8(-4.8,2.4) A9(-4.8,3.2) B1(-4,-3.2) B2(-4,-2.4) B3(-4,-1.6) B7(-4,1.6) B8(-4,2.4) B9(-4,3.2) C1(-3.2,-3.2) C2(-3.2,-2.4) C3(-3.2,-1.6) C7(-3.2,1.6) C8(-3.2,2.4) C9(-3.2,3.2) D1(-2.4,-3.2) D2(-2.4,-2.4) D3(-2.4,-1.6) D7(-2.4,1.6) D8(-2.4,2.4) D9(-2.4,3.2) E1(-1.6,-3.2) E2(-1.6,-2.4) E3(-1.6,-1.6) E7(-1.6,1.6) E8(-1.6,2.4) E9(-1.6,3.2) F1(-0.8,-3.2) F2(-0.8,-2.4) F3(-0.8,-1.6) F7(-0.8,1.6) F8(-0.8,2.4) F9(-0.8,3.2) G1(0,-3.2) G2(0,-2.4) G3(0,-1.6) G7(0,1.6) G8(0,2.4) G9(0,3.2) H1(0.8,-3.2) H2(0.8,-2.4) H3(0.8,-1.6) H7(0.8,1.6) H8(0.8,2.4) H9(0.8,3.2) J1(1.6,-3.2) J2(1.6,-2.4) J3(1.6,-1.6) J7(1.6,1.6) J8(1.6,2.4) J9(1.6,3.2) K1(2.4,-3.2) K2(2.4,-2.4) K3(2.4,-1.6) K7(2.4,1.6) K8(2.4,2.4) K9(2.4,3.2) L1(3.2,-3.2) L2(3.2,-2.4) L3(3.2,-1.6) L7(3.2,1.6) L8(3.2,2.4) L9(3.2,3.2) M1(4,-3.2) M2(4,-2.4) M3(4,-1.6) M7(4,1.6) M8(4,2.4) M9(4,3.2) N1(4.8,-3.2) N2(4.8,-2.4) N3(4.8,-1.6) N7(4.8,1.6) N8(4.8,2.4) N9(4.8,3.2)
BGA169-BGA153-0_5MM
  round 1.016 smd: 1(-12.413,-6.351) 2(13.363,-0.028)
  round 0.254 smd: A4(-6.75,-1.75) A6(-6.75,-0.75) A9(-6.75,0.75) A11(-6.75,1.75) AA2(3.25,-2.75) AA3(3.25,-2.25) AA4(3.25,-1.75) AA5(3.25,-1.25) AA6(3.25,-0.75) AA7(3.25,-0.25) AA8(3.25,0.25) AA9(3.25,0.75) AA10(3.25,1.25) AA11(3.25,1.75) AA12(3.25,2.25) AA13(3.25,2.75) AA14(3.25,3.25) AE1(5.25,-3.25) AE14(5.25,3.25) AG2(6.25,-2.75) AG13(6.25,2.75) AH4(6.75,-1.75) AH6(6.75,-0.75) AH9(6.75,0.75) AH11(6.75,1.75) B2(-6.25,-2.75) B13(-6.25,2.75) D1(-5.25,-3.25) D14(-5.25,3.25) H8(-3.25,0.25) H9(-3.25,0.75) H10(-3.25,1.25) H11(-3.25,1.75) H12(-3.25,2.25) H13(-3.25,2.75) H14(-3.25,3.25) J2(-2.75,-2.75) J3(-2.75,-2.25) J4(-2.75,-1.75) J5(-2.75,-1.25) J6(-2.75,-0.75) J7(-2.75,-0.25) J8(-2.75,0.25) J9(-2.75,0.75) J10(-2.75,1.25) J11(-2.75,1.75) J12(-2.75,2.25) J13(-2.75,2.75) J14(-2.75,3.25) K2(-2.25,-2.75) K3(-2.25,-2.25) K4(-2.25,-1.75) K5(-2.25,-1.25) K6(-2.25,-0.75) K7(-2.25,-0.25) K8(-2.25,0.25) K9(-2.25,0.75) K10(-2.25,1.25) K11(-2.25,1.75) K12(-2.25,2.25) K13(-2.25,2.75) K14(-2.25,3.25) L2(-1.75,-2.75) L3(-1.75,-2.25) L4(-1.75,-1.75) L12(-1.75,2.25) L13(-1.75,2.75) L14(-1.75,3.25) M1(-1.25,-3.25) M2(-1.25,-2.75) M3(-1.25,-2.25) M5(-1.25,-1.25) M6(-1.25,-0.75) M7(-1.25,-0.25) M8(-1.25,0.25) M9(-1.25,0.75) M10(-1.25,1.25) M12(-1.25,2.25) M13(-1.25,2.75) M14(-1.25,3.25) N1(-0.75,-3.25) N2(-0.75,-2.75) N3(-0.75,-2.25) N5(-0.75,-1.25) N10(-0.75,1.25) N12(-0.75,2.25) N13(-0.75,2.75) N14(-0.75,3.25) P1(-0.25,-3.25) P2(-0.25,-2.75) P3(-0.25,-2.25) P5(-0.25,-1.25) P10(-0.25,1.25) P12(-0.25,2.25) P13(-0.25,2.75) P14(-0.25,3.25) R1(0.25,-3.25) R2(0.25,-2.75) R3(0.25,-2.25) R5(0.25,-1.25) R10(0.25,1.25) R12(0.25,2.25) R13(0.25,2.75) R14(0.25,3.25) T1(0.75,-3.25) T2(0.75,-2.75) T3(0.75,-2.25) T5(0.75,-1.25) T10(0.75,1.25) T12(0.75,2.25) T13(0.75,2.75) T14(0.75,3.25) U1(1.25,-3.25) U2(1.25,-2.75) U3(1.25,-2.25) U5(1.25,-1.25) U6(1.25,-0.75) U7(1.25,-0.25) U8(1.25,0.25) U9(1.25,0.75) U10(1.25,1.25) U12(1.25,2.25) U13(1.25,2.75) U14(1.25,3.25) V1(1.75,-3.25) V2(1.75,-2.75) V3(1.75,-2.25) V12(1.75,2.25) V13(1.75,2.75) V14(1.75,3.25) W1(2.25,-3.25) W2(2.25,-2.75) W3(2.25,-2.25) W4(2.25,-1.75) W5(2.25,-1.25) W6(2.25,-0.75) W7(2.25,-0.25) W8(2.25,0.25) W9(2.25,0.75) W10(2.25,1.25) W11(2.25,1.75) W12(2.25,2.25) W13(2.25,2.75) W14(2.25,3.25) Y2(2.75,-2.75) Y3(2.75,-2.25) Y4(2.75,-1.75) Y5(2.75,-1.25) Y6(2.75,-0.75) Y7(2.75,-0.25) Y8(2.75,0.25) Y9(2.75,0.75) Y10(2.75,1.25) Y11(2.75,1.75) Y12(2.75,2.25) Y13(2.75,2.75) Y14(2.75,3.25)
  oval 0.203x0.254 smd: AA1(3.25,-3.25) H1(-3.25,-3.25) J1(-2.75,-3.25) K1(-2.25,-3.25) L1(-1.75,-3.25) Y1(2.75,-3.25)
  oval 0.254x0.203 smd: H2(-3.25,-2.75) H3(-3.25,-2.25) H4(-3.25,-1.75) H5(-3.25,-1.25) H6(-3.25,-0.75) H7(-3.25,-0.25)
CDTWIFI
  rect 1.981x1.524 smd: 1(6.087,4.005) 5(6.087,-4.795)
  rect 1.981x1.321 smd: 2(6.087,1.505) 4(6.087,-1.995)
  rect 2.184x1.27 smd: 3(6.189,-0.245)
  rect 2.489x1.397 smd: 6(-6.341,4.5) 7(-6.341,2.5)
CDTWIFI10
  oval 2.54x1.397 smd: 1(-6.1,4.121) 2(-6.1,2.121) 3(-6.1,-0.856) 4(-6.1,-3.015)
  oval 2.032x1.397 smd: 5(6.1,3.621) 6(6.1,1.121) 7(6.1,-2.379) 8(6.1,-5.179)
  oval 1.397x2.54 smd: 9(3.654,-6.5) 10(2.384,-6.5)
DC-002
  oval 2.997x1.803 hole 1.524x0.813: 1(0,0) 2(0,5)
  oval 1.803x2.997 hole 0.813x1.524: 3(-2.7,2.8)
DFN2510P10E
  oval 0.254x0.813 smd: 1(-1,-0.525) 5(1,-0.525) 6(1,0.525) 10(-1,0.525)
  oval 0.229x0.813 smd: 2(-0.5,-0.525) 4(0.5,-0.525) 7(0.5,0.525) 9(-0.5,0.525)
  oval 0.356x0.813 smd: 3(0,-0.525) 8(0,0.525)
HOLE182-142
  round 4.623 hole 3.607: 1(0,0)
HSC0402
  rect 0.508x0.508 smd: 1(-0.406,0) 2(0.406,0)
HSCOX-AMC-TM-A
  rect 0.813x0.813 smd: 1(0,1.35)
  rect 1.168x2.184 smd: 2(-1.326,0) 3(1.326,0)
HSOD323A
  rect 1.118x0.508 smd: 1(1.372,0) 2(-1.372,0)
HSOT-SC70
  rect 0.457x1.016 smd: 1(-0.65,-0.94) 2(0.65,-0.94) 3(0,0.94)
HSR0402
  rect 0.508x0.508 smd: 1(-0.406,0) 2(0.406,0)
ID-BOARD
  round 1.016 smd: 1(0,0)
LED3C-100C
  rect 1.524x1.524 hole 0.965: 1(0,0)
  round 1.524 hole 0.965: 2(2.54,0) 3(5.08,0)
MICRO_SD8-PUSH
  rect 0.813x1.27 smd: 1(2.9,-5.605) 2(1.8,-5.605) 3(0.7,-5.605) 4(-0.4,-5.605) 5(-1.5,-5.605) 6(-2.6,-5.605) 7(-3.7,-5.605) 8(-4.8,-5.605)
  rect 1.27x1.27 smd: 9(-6.74,-2.975) 10(-6.74,6.025)
  rect 1.524x1.143 smd: 11(-4.94,7.15) 12(2.84,7.15)
  rect 1.524x2.286 smd: 13(6.97,6.355) 15(-6.97,-5.125)
  rect 1.524x2.54 smd: 14(6.97,-4.975)
MJ8-RLY
  round 3.429 hole 3.429 unplated: (-2.794,2.54) (9.906,2.54)
  round 1.27 hole 0.914: 1(0,0) 2(1.016,-1.778) 3(2.032,0) 4(3.048,-1.778) 5(4.064,0) 6(5.08,-1.778) 7(6.096,0) 8(7.112,-1.778) 9(-3.302,-6.604) 10(-1.016,-6.604) 11(8.128,-6.604) 12(10.414,-6.604)
PWC3-RF-A
  rect 1.778x3.962 hole 0.762x2.946: 1(0,0)
  oval 3.454x1.778 hole 2.438x0.762: 2(2.3,4.8)
  oval 1.676x3.454 hole 0.66x2.438: 3(5.8,0)
RN8-0402
  rect 0.305x0.559 smd: 1(-0.762,-0.483) 4(0.762,-0.483) 5(0.762,0.483) 8(-0.762,0.483)
  rect 0.254x0.559 smd: 2(-0.254,-0.483) 3(0.254,-0.483) 6(0.254,0.483) 7(-0.254,0.483)
SAC6666
  rect 3.175x1.016 smd: 1(-2.5,0) 2(2.5,0)
SC0402
  rect 0.508x0.508 smd: 1(-0.406,0) 2(0.406,0)
SC0603
  rect 0.762x0.813 smd: 1(-0.699,0) 2(0.699,0)
SC0805
  rect 0.991x1.27 smd: 1(-0.813,0) 2(0.813,0)
SC1206
  rect 1.295x1.651 smd: 1(-1.346,0) 2(1.346,0)
SEN3-100C
  rect 1.27x1.27 hole 0.813: 1(-2.54,0)
  round 1.27 hole 0.813: 2(0,0) 3(2.54,0)
SGM8903
  rect 0.356x1.524 smd: 1(-1.95,-2.921) 2(-1.3,-2.921) 3(-0.65,-2.921) 4(0,-2.921) 5(0.65,-2.921) 6(1.3,-2.921) 7(1.95,-2.921) 8(1.95,2.921) 9(1.3,2.921) 10(0.65,2.921) 11(0,2.921) 12(-0.65,2.921) 13(-1.3,2.921) 14(-1.95,2.921)
SIP12-2_0MM-1827
  oval 3.175x1.524 hole 1.016: 1(-13.5,5.005) 2(-13.5,3.005) 3(-13.5,1.005) 4(-13.5,-0.995) 5(-13.5,-2.995) 6(-13.5,-4.995)
  oval 2.032x1.27 hole 1.016: 7(13.5,-5.604) 8(13.5,-4.104) 9(13.5,-2.604) 10(13.5,2.681) 11(13.5,4.181) 12(13.5,5.681)
SIP-1P
  round 1.651 hole 0.914: 1(0,0)
SL0402
  rect 0.483x0.508 smd: 1(-0.394,0) 2(0.394,0)
SL0603
  rect 0.711x0.813 smd: 1(-0.74,0) 2(0.74,0)
SL0805
  rect 0.94x1.27 smd: 1(-0.851,0) 2(0.851,0)
SOIC8N
  rect 0.635x1.905 smd: 1(-1.905,-2.6) 2(-0.635,-2.6) 3(0.635,-2.6) 4(1.905,-2.6) 5(1.905,2.6) 6(0.635,2.6) 7(-0.635,2.6) 8(-1.905,2.6)
  rect 3.505x2.616 smd: 9(0,0)
SOP8H-50-200
  rect 0.635x1.905 smd: 1(-1.905,-2.667) 2(-0.635,-2.667) 3(0.635,-2.667) 4(1.905,-2.667) 5(1.905,2.667) 6(0.635,2.667) 7(-0.635,2.667) 8(-1.905,2.667)
  rect 2.286x2.286 smd: 9(0,0)
SOP48-20-720B
  rect 0.254x1.473 smd: 1(-5.75,-9.802) 2(-5.25,-9.802) 3(-4.75,-9.802) 4(-4.25,-9.802) 5(-3.75,-9.802) 6(-3.25,-9.802) 7(-2.75,-9.802) 8(-2.25,-9.802) 9(-1.75,-9.802) 10(-1.25,-9.802) 11(-0.75,-9.802) 12(-0.25,-9.802) 13(0.25,-9.802) 14(0.75,-9.802) 15(1.25,-9.802) 16(1.75,-9.802) 17(2.25,-9.802) 18(2.75,-9.802) 19(3.25,-9.802) 20(3.75,-9.802) 21(4.25,-9.802) 22(4.75,-9.802) 23(5.25,-9.802) 24(5.75,-9.802) 25(5.75,9.802) 26(5.25,9.802) 27(4.75,9.802) 28(4.25,9.802) 29(3.75,9.802) 30(3.25,9.802) 31(2.75,9.802) 32(2.25,9.802) 33(1.75,9.802) 34(1.25,9.802) 35(0.75,9.802) 36(0.25,9.802) 37(-0.25,9.802) 38(-0.75,9.802) 39(-1.25,9.802) 40(-1.75,9.802) 41(-2.25,9.802) 42(-2.75,9.802) 43(-3.25,9.802) 44(-3.75,9.802) 45(-4.25,9.802) 46(-4.75,9.802) 47(-5.25,9.802) 48(-5.75,9.802)
SOT23
  rect 1.016x1.27 smd: 1(-1.016,-1.143) 2(1.016,-1.143) 3(0,1.143)
SOT23-5
  rect 0.711x1.016 smd: 1(-0.95,-1.3) 2(0,-1.3) 3(0.95,-1.3) 4(0.95,1.3) 5(-0.95,1.3)
SOT23_5
  rect 0.635x1.27 smd: 1(-0.95,-1.2) 2(0,-1.2) 3(0.95,-1.2) 4(0.95,1.2) 5(-0.95,1.2)
SOT23_6
  rect 0.635x1.397 smd: 1(-0.95,-1.2) 2(0,-1.2) 3(0.95,-1.2) 4(0.95,1.2) 5(0,1.2) 6(-0.95,1.2)
SOT23A-6L
  rect 0.635x1.27 smd: 1(-0.95,-1.25) 2(0,-1.25) 3(0.95,-1.25) 4(0.95,1.25) 5(0,1.25) 6(-0.95,1.25)
SPSW6-T
  rect 1.829x1.118 smd: 1(-3.1,1.85) 2(3.1,1.85) 3(-3.1,-1.85) 4(3.1,-1.85)
  rect 1.397x0.61 smd: 5(0,2.5) 6(0,-2.5)
SR0402
  rect 0.508x0.508 smd: 1(-0.406,0) 2(0.406,0)
SR0603
  rect 0.711x0.813 smd: 1(-0.737,0) 2(0.737,0)
SR0805
  rect 0.838x1.143 smd: 1(-0.927,0) 2(0.927,0)
SR1206
  rect 1.295x1.6 smd: 1(-1.346,0) 2(1.346,0)
SRN8-0804
  rect 0.279x0.533 smd: 1(-0.762,-0.521) 2(-0.254,-0.521) 3(0.254,-0.521) 4(0.762,-0.521) 5(0.762,0.521) 6(0.254,0.521) 7(-0.254,0.521) 8(-0.762,0.521)
STFM16-50-285
  rect 0.635x1.905 smd: 1(-4.445,-4.381) 2(-3.175,-4.381) 3(-1.905,-4.381) 4(-0.635,-4.381) 5(0.635,-4.381) 6(1.905,-4.381) 7(3.175,-4.381) 8(4.445,-4.381) 9(4.445,4.381) 10(3.175,4.381) 11(1.905,4.381) 12(0.635,4.381) 13(-0.635,4.381) 14(-1.905,4.381) 15(-3.175,4.381) 16(-4.445,4.381)
SWPA4020S
  rect 1.905x3.683 smd: 1(-1.55,0) 2(1.55,0)
SWPA5040S
  rect 1.397x4.191 smd: 1(-1.85,0) 2(1.85,0)
TFBGA395-32-2323
  round 0.356 smd: A1(-8.8,-8.8) A2(-8.8,-8) A3(-8.8,-7.2) A4(-8.8,-6.4) A6(-8.8,-4.8) A8(-8.8,-3.2) A9(-8.8,-2.4) A11(-8.8,-0.8) A12(-8.8,0) A15(-8.8,2.4) A17(-8.8,4) A19(-8.8,5.6) A20(-8.8,6.4) A22(-8.8,8) A23(-8.8,8.8) AA1(7.2,-8.8) AA2(7.2,-8) AA3(7.2,-7.2) AA4(7.2,-6.4) AA5(7.2,-5.6) AA6(7.2,-4.8) AA7(7.2,-4) AA8(7.2,-3.2) AA9(7.2,-2.4) AA10(7.2,-1.6) AA11(7.2,-0.8) AA12(7.2,0) AA13(7.2,0.8) AA14(7.2,1.6) AA15(7.2,2.4) AA16(7.2,3.2) AA17(7.2,4) AA18(7.2,4.8) AA19(7.2,5.6) AA20(7.2,6.4) AA21(7.2,7.2) AA22(7.2,8) AA23(7.2,8.8) AB1(8,-8.8) AB2(8,-8) AB3(8,-7.2) AB4(8,-6.4) AB5(8,-5.6) AB6(8,-4.8) AB7(8,-4) AB8(8,-3.2) AB9(8,-2.4) AB10(8,-1.6) AB11(8,-0.8) AB12(8,0) AB13(8,0.8) AB14(8,1.6) AB15(8,2.4) AB16(8,3.2) AB18(8,4.8) AB20(8,6.4) AB22(8,8) AB23(8,8.8) AC1(8.8,-8.8) AC2(8.8,-8) AC3(8.8,-7.2) AC5(8.8,-5.6) AC6(8.8,-4.8) AC8(8.8,-3.2) AC9(8.8,-2.4) AC11(8.8,-0.8) AC12(8.8,0) AC14(8.8,1.6) AC15(8.8,2.4) AC18(8.8,4.8) AC20(8.8,6.4) AC22(8.8,8) AC23(8.8,8.8) B1(-8,-8.8) B2(-8,-8) B3(-8,-7.2) B4(-8,-6.4) B6(-8,-4.8) B7(-8,-4) B8(-8,-3.2) B9(-8,-2.4) B11(-8,-0.8) B12(-8,0) B14(-8,1.6) B15(-8,2.4) B17(-8,4) B19(-8,5.6) B20(-8,6.4) B22(-8,8) B23(-8,8.8) C1(-7.2,-8.8) C2(-7.2,-8) C3(-7.2,-7.2) C4(-7.2,-6.4) C5(-7.2,-5.6) C6(-7.2,-4.8) C7(-7.2,-4) C8(-7.2,-3.2) C9(-7.2,-2.4) C10(-7.2,-1.6) C11(-7.2,-0.8) C12(-7.2,0) C13(-7.2,0.8) C14(-7.2,1.6) C15(-7.2,2.4) C16(-7.2,3.2) C17(-7.2,4) C18(-7.2,4.8) C19(-7.2,5.6) C20(-7.2,6.4) C21(-7.2,7.2) C22(-7.2,8) D3(-6.4,-7.2) D4(-6.4,-6.4) D5(-6.4,-5.6) D6(-6.4,-4.8) D7(-6.4,-4) D8(-6.4,-3.2) D9(-6.4,-2.4) D10(-6.4,-1.6) D11(-6.4,-0.8) D12(-6.4,0) D13(-6.4,0.8) D14(-6.4,1.6) D15(-6.4,2.4) D16(-6.4,3.2) D17(-6.4,4) D18(-6.4,4.8) D19(-6.4,5.6) D20(-6.4,6.4) D21(-6.4,7.2) D22(-6.4,8) E1(-5.6,-8.8) E2(-5.6,-8) E3(-5.6,-7.2) E4(-5.6,-6.4) E5(-5.6,-5.6) E6(-5.6,-4.8) E15(-5.6,2.4) E16(-5.6,3.2) E17(-5.6,4) E18(-5.6,4.8) E19(-5.6,5.6) E20(-5.6,6.4) E21(-5.6,7.2) E22(-5.6,8) E23(-5.6,8.8) F1(-4.8,-8.8) F2(-4.8,-8) F3(-4.8,-7.2) F4(-4.8,-6.4) F5(-4.8,-5.6) F19(-4.8,5.6) F20(-4.8,6.4) F21(-4.8,7.2) G3(-4,-7.2) G4(-4,-6.4) G5(-4,-5.6) G10(-4,-1.6) G11(-4,-0.8) G12(-4,0) G13(-4,0.8) G14(-4,1.6) G15(-4,2.4) G16(-4,3.2) G17(-4,4) G19(-4,5.6) G20(-4,6.4) G21(-4,7.2) H1(-3.2,-8.8) H2(-3.2,-8) H3(-3.2,-7.2) H4(-3.2,-6.4) H5(-3.2,-5.6) H10(-3.2,-1.6) H11(-3.2,-0.8) H12(-3.2,0) H13(-3.2,0.8) H14(-3.2,1.6) H15(-3.2,2.4) H16(-3.2,3.2) H17(-3.2,4) H19(-3.2,5.6) H20(-3.2,6.4) H21(-3.2,7.2) H22(-3.2,8) H23(-3.2,8.8) J2(-2.4,-8) J3(-2.4,-7.2) J4(-2.4,-6.4) J5(-2.4,-5.6) J6(-2.4,-4.8) J7(-2.4,-4) J10(-2.4,-1.6) J11(-2.4,-0.8) J12(-2.4,0) J13(-2.4,0.8) J14(-2.4,1.6) J15(-2.4,2.4) J16(-2.4,3.2) J17(-2.4,4) J19(-2.4,5.6) J20(-2.4,6.4) J21(-2.4,7.2) J22(-2.4,8) J23(-2.4,8.8) K1(-1.6,-8.8) K2(-1.6,-8) K3(-1.6,-7.2) K4(-1.6,-6.4) K5(-1.6,-5.6) K6(-1.6,-4.8) K7(-1.6,-4) K10(-1.6,-1.6) K11(-1.6,-0.8) K12(-1.6,0) K13(-1.6,0.8) K14(-1.6,1.6) K15(-1.6,2.4) K16(-1.6,3.2) K17(-1.6,4) K19(-1.6,5.6) K20(-1.6,6.4) K21(-1.6,7.2) L1(-0.8,-8.8) L2(-0.8,-8) L3(-0.8,-7.2) L4(-0.8,-6.4) L5(-0.8,-5.6) L6(-0.8,-4.8) L10(-0.8,-1.6) L11(-0.8,-0.8) L12(-0.8,0) L13(-0.8,0.8) L14(-0.8,1.6) L15(-0.8,2.4) L16(-0.8,3.2) L17(-0.8,4) L19(-0.8,5.6) L20(-0.8,6.4) L21(-0.8,7.2) L22(-0.8,8) L23(-0.8,8.8) M2(0,-8) M3(0,-7.2) M4(0,-6.4) M5(0,-5.6) M6(0,-4.8) M8(0,-3.2) M10(0,-1.6) M11(0,-0.8) M12(0,0) M13(0,0.8) M14(0,1.6) M15(0,2.4) M16(0,3.2) M17(0,4) M19(0,5.6) M20(0,6.4) M21(0,7.2) N1(0.8,-8.8) N2(0.8,-8) N3(0.8,-7.2) N4(0.8,-6.4) N5(0.8,-5.6) N6(0.8,-4.8) N8(0.8,-3.2) N10(0.8,-1.6) N11(0.8,-0.8) N12(0.8,0) N13(0.8,0.8) N14(0.8,1.6) N15(0.8,2.4) N16(0.8,3.2) N17(0.8,4) N19(0.8,5.6) N20(0.8,6.4) N21(0.8,7.2) N22(0.8,8) N23(0.8,8.8) P1(1.6,-8.8) P2(1.6,-8) P3(1.6,-7.2) P4(1.6,-6.4) P5(1.6,-5.6) P6(1.6,-4.8) P10(1.6,-1.6) P11(1.6,-0.8) P12(1.6,0) P13(1.6,0.8) P14(1.6,1.6) P15(1.6,2.4) P16(1.6,3.2) P17(1.6,4) P19(1.6,5.6) P20(1.6,6.4) P21(1.6,7.2) R2(2.4,-8) R3(2.4,-7.2) R4(2.4,-6.4) R5(2.4,-5.6) R6(2.4,-4.8) R16(2.4,3.2) R17(2.4,4) R19(2.4,5.6) R20(2.4,6.4) R21(2.4,7.2) R22(2.4,8) R23(2.4,8.8) T1(3.2,-8.8) T2(3.2,-8) T3(3.2,-7.2) T4(3.2,-6.4) T5(3.2,-5.6) T6(3.2,-4.8) T9(3.2,-2.4) T10(3.2,-1.6) T11(3.2,-0.8) T12(3.2,0) T17(3.2,4) T19(3.2,5.6) T20(3.2,6.4) T21(3.2,7.2) U1(4,-8.8) U2(4,-8) U3(4,-7.2) U4(4,-6.4) U5(4,-5.6) U6(4,-4.8) U7(4,-4) U20(4,6.4) U21(4,7.2) U22(4,8) U23(4,8.8) V2(4.8,-8) V3(4.8,-7.2) V4(4.8,-6.4) V5(4.8,-5.6) V6(4.8,-4.8) V7(4.8,-4) V8(4.8,-3.2) V9(4.8,-2.4) V10(4.8,-1.6) V11(4.8,-0.8) V12(4.8,0) V13(4.8,0.8) V14(4.8,1.6) V20(4.8,6.4) V21(4.8,7.2) W1(5.6,-8.8) W2(5.6,-8) W3(5.6,-7.2) W4(5.6,-6.4) W5(5.6,-5.6) W6(5.6,-4.8) W7(5.6,-4) W8(5.6,-3.2) W9(5.6,-2.4) W10(5.6,-1.6) W11(5.6,-0.8) W12(5.6,0) W13(5.6,0.8) W14(5.6,1.6) W15(5.6,2.4) W16(5.6,3.2) W17(5.6,4) W18(5.6,4.8) W19(5.6,5.6) W20(5.6,6.4) W21(5.6,7.2) W22(5.6,8) W23(5.6,8.8) Y1(6.4,-8.8) Y2(6.4,-8) Y3(6.4,-7.2) Y4(6.4,-6.4) Y5(6.4,-5.6) Y6(6.4,-4.8) Y7(6.4,-4) Y8(6.4,-3.2) Y9(6.4,-2.4) Y10(6.4,-1.6) Y11(6.4,-0.8) Y12(6.4,0) Y13(6.4,0.8) Y14(6.4,1.6) Y15(6.4,2.4) Y16(6.4,3.2) Y17(6.4,4) Y18(6.4,4.8) Y19(6.4,5.6) Y20(6.4,6.4) Y21(6.4,7.2) Y22(6.4,8) Y23(6.4,8.8)
TSW4-RG-C
  round 1.524 hole 1.016: 1(0,0) 2(4.5,0)
  round 2.032 hole 1.321: 3(-1.25,2.5) 4(5.75,2.5)
unnamed#2
  round 1.016 smd: 1(0,0)
unnamed#3
  round 1.016 hole 1.016 unplated: (-3,1.13) (-1.5,1.13) (0,1.13) (1.5,1.13) (3,1.13)
unnamed#4
  round 2.032 hole 2.032 unplated: (0,0)
USB3_0_9P_DIP_MAINSUPER
  round 1.245 hole 0.762: 1(0,0) 2(2.5,0) 3(4.5,0) 4(7,0) 5(7.5,1.5) 6(5.5,1.5) 7(3.5,1.5) 8(1.5,1.5) 9(-0.5,1.5)
  round 2.896 hole 2.413: 10(-3.07,-2) 11(10.07,-2)
USB4-1415
  rect 1.27x1.905 hole 1.016: 1(0,0)
  oval 1.27x1.905 hole 1.016: 2(2.5,0) 3(4.5,0) 4(7,0)
  round 3.048 hole 2.286: 5(-3.07,-2.71) 6(10.07,-2.71)
VAF6-1107
  round 1.016 hole 1.016 unplated: (1.7,2.3) (8.5,2.3)
  rect 2.159x1.626 hole 1.321x0.61: 2(0,0)
  oval 2.159x1.626 hole 1.321x0.61: 3(3,0)
  oval 2.337x1.626 hole 1.321x0.61: 4(7,0.2) 5(8.6,4.6) 6(0,5.6)
WBC0104-49T
  oval 0.762x1.143 hole 0.508: 1(0,0) 2(1.25,0) 3(2.5,0) 4(3.75,0)
WBC0119-20R-A
  round 1.092 hole 1.092 unplated: (-2.5,2.745) (2.5,2.745)
  rect 0.254x2.591 smd: 1(4.5,5.155) 2(4,5.155) 3(3.5,5.155) 4(3,5.155) 5(2.5,5.155) 6(2,5.155) 7(1.5,5.155) 8(1,5.155) 9(0.5,5.155) 10(0,5.155) 11(-0.5,5.155) 12(-1,5.155) 13(-1.5,5.155) 14(-2,5.155) 15(-2.5,5.155) 16(-3,5.155) 17(-3.5,5.155) 18(-4,5.155) 19(-4.5,5.155)
  oval 1.524x3.302 hole 0.914x2.667: 20(-7.25,4.395) 21(7.25,4.395)
  oval 1.524x2.794 hole 0.914x2.083: 22(-7.25,-1.565) 23(7.25,-1.565)
X288
  rect 1.651x1.27 smd: 1(-1.15,-0.85) 2(1.15,-0.85) 3(1.15,0.85) 4(-1.15,0.85)

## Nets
1V1_CORE: C1.1 C19.1 C34.1 C37.1 C51.1 C82.2 C90.1 C107.1 C120.1 C121.1 C127.1 C189.1 C193.1 C282.1 L3.2 LB11.1 LB12.2 LB21.1 LB31.1 R101.2 U1.J13 U1.J14 U1.K13 U1.K14 U1.L10 U1.L13 U1.L14 U1.M10 U1.M13 U1.M14 U1.N10 U1.N11 U1.N12 U1.N13 U1.N14 U1.P10 U1.P11 U1.P12 U1.P13 U1.P14 U1.P15
1V1_CPU: C28.1 C31.1 C35.1 C41.1 C76.2 C116.1 C132.1 C135.1 C138.1 C243.1 C257.1 L2.2 R53.2 U1.H16 U1.H17 U1.J16 U1.J17 U1.K17 U1.L16 U1.L17 U1.M16 U1.M17
1V5_DDR3: C20.1 C40.1 C68.1 C84.2 C88.1 C89.1 C94.1 C95.1 C96.1 C97.1 C98.1 C99.1 C100.1 C101.1 C102.1 C103.1 C104.1 C106.1 C110.1 C117.1 C126.1 C128.1 C129.1 C130.1 C131.1 C133.1 C134.1 C137.1 C139.1 C144.1 C151.1 C152.1 C161.1 C162.1 C167.1 C168.1 C169.1 C180.1 C181.1 C200.1 C202.1 C204.1 C205.1 C208.1 C209.1 C210.1 C212.1 C213.1 C216.1 C218.1 C219.1 C220.1 C221.1 C224.1 C226.1 C227.1 C228.1 C232.1 C234.1 C236.1 C237.1 C238.1 C241.1 C249.1 C278.1 C279.1 C284.1 C285.1 C286.1 C287.1 C288.1 C289.1 C290.1 C291.1 C306.1 L4.2 R10.2 R24.2 R46.2 R84.1 R123.1 R129.1 R133.1 U1.J6 U1.J7 U1.K6 U1.K7 U1.L6 U1.N6 U1.P6 U1.T6 U1.T9 U1.T10 U1.U6 U1.U7 U1.V5 U1.V6 U1.V7 U1.V8 U1.V9 U1.V11 U1.V12 U1.V13 U1.V14 U1.W4 U1.W5 U1.W6 U1.W7 U1.Y4 U1.Y5 U1.Y6 U3.A2 U3.A9 U3.B9 U3.C1 U3.D7 U3.E2 U3.E9 U3.G2 U3.G8 U3.K1 U3.K9 U3.M1 U3.M9 U6.A2 U6.A9 U6.B9 U6.C1 U6.D7 U6.E2 U6.E9 U6.G2 U6.G8 U6.K1 U6.K9 U6.M1 U6.M9 U20.A2 U20.A9 U20.B9 U20.C1 U20.D7 U20.E2 U20.E9 U20.G2 U20.G8 U20.K1 U20.K9 U20.M1 U20.M9 U21.A2 U21.A9 U21.B9 U21.C1 U21.D7 U21.E2 U21.E9 U21.G2 U21.G8 U21.K1 U21.K9 U21.M1 U21.M9 U28.1
3V3: C2.1 C4.1 C13.1 C25.1 C26.1 C27.1 C39.1 C46.1 C53.1 C67.1 C69.1 C91.1 C108.1 C114.1 J18.4 L5.2 Q13.2 R2.1 R3.1 R6.1 R34.1 R60.1 R88.2 R105.2 R135.1 R136.1 R140.2 R178.2 U1.V20 U1.W20 U11.4 U13.4 U15.4
3V3_MOS: C73.1 C74.1 C197.1 C198.1 C199.1 C245.1 C283.1 D4.2 D9.2 D19.2 J25.10 J25.12 LB1.2 LB4.2 LB7.2 LB8.2 LB14.1 LB17.2 LB18.1 LB20.1 LB22.1 LB35.1 Q13.3 Q15.2 R26.1 R30.1 R44.2 R47.1 R77.1 R83.2 R86.1 R92.1 R155.1 U1.D10 U1.D11 U1.D12 U1.E18 U1.F5 U1.H19 U1.J19 U1.M19 U1.N19
3V3_MOS_FLASH: C36.1 C63.1 C92.1 C93.1 C105.1 C142.1 C143.1 C275.1 C323.1 C324.1 D4.1 R12.1 R29.1 R58.1 R68.2 R80.1 R92.2 R93.1 R176.1 R177.1 R188.1 R189.1 R202.1 R203.1 R212.1 R215.1 U19.1 U19.12 U19.24 U19.34 U19.37 U22.AA3 U22.AA5 U22.K6 U22.M6 U22.N5 U22.T10 U22.U9 U22.W4 U22.Y4
3V3_SD: C263.1 C391.1 J21.4 Q15.3 R86.2 R210.1
3V3_WIFI: C21.1 C62.1 J2.5 LB4.1 U2.5 U7.8
5V0: C6.1 C58.1 C59.1 C111.1 C112.1 D2.2 J1.1 J10.1 Q14.2 R4.1 R144.1 U14.2
5V0_MOS: C56.1 C70.1 C195.1 C305.1 D20.2 LB2.2 LB3.2 Q14.3 R15.2 R16.2 R179.1 U10.1 U12.1 U28.6
5V0_MOS_HDMI: C150.1 D20.1 J26.18 R186.2 R187.2 U4.5
AVDD11_PLL012: C12.1 C185.1 LB21.2 U1.P17
AVDD11_USB3: C16.1 C48.1 LB11.2 U1.R16 U1.R17 U1.T17
AVDD33_ADAC: C188.1 C194.1 LB35.2 U1.E19
AVDD33_PLL01: C14.1 C186.1 LB22.2 U1.R19
AVDD33_USB2: C3.1 LB17.1 U1.K19
AVDD33_USB3: C18.1 LB18.2 U1.W17 U1.W18
